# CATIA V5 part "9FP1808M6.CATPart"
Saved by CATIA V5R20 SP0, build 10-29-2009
Part number: 9FP1808M6
Revision: ANY
Definition: UNKNOWN
Nomenclature: 9FP1808M6
Source: Unknown
Bounding box of the stored display mesh (mm): x -8.9 to 8.9, y 0 to 8, z -8.9 to 8.9
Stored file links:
  C:\Users\Utente\Desktop\IO LAVORO\3D X SITO CF\CUMSA\3D files PW\pw101830\pw101830_ejection\9FP1808M6.CATPart
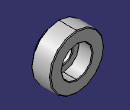
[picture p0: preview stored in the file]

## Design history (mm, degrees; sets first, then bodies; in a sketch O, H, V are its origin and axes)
Body1 "Chaflán1" (main body)
  Solid1: solid without history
